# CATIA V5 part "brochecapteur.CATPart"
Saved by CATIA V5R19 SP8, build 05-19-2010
Part number: brochecapteur
Revision: ANY
Definition: UNKNOWN
Nomenclature: brochecapteur
Source: Unknown
Bounding box of the stored display mesh (mm): x -6.375 to 6.375, y -2.885 to 2.885, z -6.35 to 0.8
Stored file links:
  D:\Documents\1_Travail\1 - ac-limoges.fr\ac-limoges.fr\Emmanuel Maynard - STI2D_Turgot\2 -2I2D\2_SEQUENCE_Serrure_Biométrique\5-Spé_ITEC\Serrure_Bio_Eleve\brochecapteur.CATPart
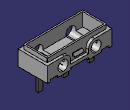
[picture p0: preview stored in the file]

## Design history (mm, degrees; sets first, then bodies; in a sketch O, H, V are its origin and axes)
Body1 "Enlèv. mat.-Extru.3" (main body)
  Solid1: solid without history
